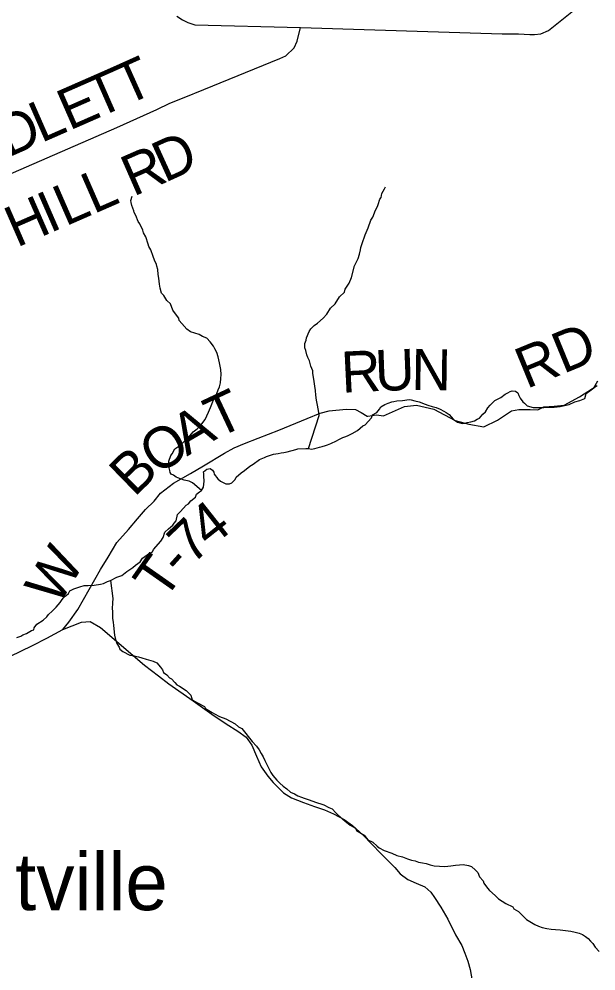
# Model space of a CAD drawing. Extents: x 1310247 to 1664935, y 235267 to 584339.
# Drawn here: x 1471891 to 1476105, y 339195 to 346148 of the extents above; entities that cross this region are included whole.
import ezdxf

# ---------------------------------------------------------------- set-up
doc = ezdxf.new("R2010")
doc.units = 0
for name, color, linetype in [('GM_X_County_Road', 7, 'Continuous'), ('GM_X_Minor_River', 7, 'Continuous'), ('GM_X_Township_Road', 7, 'Continuous'), ('GM_X_Township_Road_Text', 7, 'Continuous'), ('GM_X_Unincorporated_Text', 7, 'Continuous')]:
    doc.layers.add(name, color=color, linetype=linetype)

msp = doc.modelspace()

# ---------------------------------------------------------------- linework, layer by layer
at = {"layer": 'GM_X_County_Road'}
for points in [[(1473043.3, 346168.3), (1473084.6, 346142.9), (1473124.6, 346123), (1473175.2, 346105.6), (1473945.7, 346085.6), (1475419.6, 346041.1), (1475538.9, 346040.1), (1475621.5, 346034.4), (1475655.5, 346035.6), (1475702, 346040.1), (1475757.7, 346063.9), (1475978.4, 346238.9)], [(1471823.6, 341491.5), (1471989.8, 341571.5), (1472093.3, 341625.1), (1472210.2, 341689.5), (1472345.8, 341742.6), (1472409.4, 341748.6), (1472486.7, 341704.7), (1472806.2, 341427.6), (1472909.2, 341350.4), (1472984.9, 341291.3), (1473162.1, 341167.1), (1473298.4, 341070.2), (1473402.9, 340999), (1473489.2, 340947.5), (1473549.7, 340903.6), (1473592.2, 340843.1), (1473625.5, 340764.3), (1473658.8, 340685.5), (1473707.3, 340617.4), (1473746.6, 340570.4), (1473783, 340534.1), (1473821.8, 340495.5), (1473881.6, 340459.9), (1473968, 340424.2), (1474049.6, 340395.4), (1474123.3, 340372.4), (1474187.7, 340342.5), (1474264.8, 340302.2), (1474326.9, 340257.4), (1474401.7, 340189.5), (1474534, 340053.7), (1474636.4, 339951.3), (1474675.5, 339905.3), (1474731.9, 339862.7), (1474791.7, 339836.2), (1474853.9, 339809.8), (1474898.7, 339770.6), (1474926.3, 339731.5), (1474972.4, 339661.4), (1475021.9, 339573.9), (1475079.4, 339457.7), (1475124.2, 339380.6), (1475147.2, 339325.4), (1475170.3, 339265.6), (1475186.4, 339205.8), (1475201.3, 339121.8)]]:
    msp.add_lwpolyline(points, dxfattribs=at)
at = {"layer": 'GM_X_Minor_River'}
for points in [[(1474004.1, 343011.3), (1474082.6, 343251.8), (1474080.9, 343273.9), (1474071.9, 343328.3), (1474062.5, 343364.6), (1474059.1, 343400.8), (1474055.7, 343434.9), (1474052.3, 343467.1), (1474046.9, 343501.3), (1474041.4, 343531.5), (1474035.9, 343559.8), (1474036.2, 343577.8), (1474022.8, 343612.2), (1474013.4, 343652.5), (1473999.8, 343676.8), (1473994.1, 343695), (1473984.7, 343727.2), (1473979, 343745.4), (1473979.5, 343777.5), (1473988.1, 343803.5), (1473990.4, 343819.5), (1474009.3, 343865.3), (1474021.7, 343885.2), (1474046.2, 343908.9), (1474070.7, 343926.5), (1474111.6, 343963.9), (1474138.2, 343991.6), (1474167.1, 344035.2), (1474199.9, 344066.8), (1474230.9, 344118.5), (1474267.8, 344154), (1474274.2, 344175.9), (1474303.1, 344219.6), (1474320, 344261.4), (1474341.6, 344345.4), (1474368.7, 344399.1), (1474377.3, 344431.1), (1474383.9, 344463.1), (1474388.2, 344479), (1474396.8, 344509), (1474418.1, 344572.9), (1474434.8, 344606.7), (1474441.1, 344622.6), (1474460.2, 344678.5), (1474474.7, 344700.3), (1474493.7, 344752.2), (1474508.3, 344780), (1474514.5, 344794), (1474527.3, 344831.9), (1474535.6, 344845.8), (1474542.1, 344873.8), (1474560.8, 344907.6), (1474567.1, 344921.5)], [(1473224.7, 342703.5), (1473157.1, 342759.8), (1473133.2, 342772.2), (1473097.2, 342780.9), (1473071.2, 342789.3), (1473051.2, 342795.7), (1473037.3, 342802), (1473019.5, 342816.3), (1473001.5, 342822.7), (1472993.7, 342836.8), (1472991.9, 342850.9), (1472988.3, 342871.1), (1472984.6, 342887.2), (1472985.1, 342919.3), (1472999.9, 342959.2), (1473010.2, 342973.1), (1473029, 343008.9), (1473065.6, 343032.4), (1473100.4, 343065.9), (1473129, 343091.5), (1473163.9, 343133.1), (1473192.4, 343154.7), (1473225.3, 343192.2), (1473249.9, 343222), (1473275, 343277.7), (1473289.7, 343309.6), (1473298.2, 343335.5), (1473306.6, 343353.5), (1473315, 343373.4), (1473325.4, 343393.3), (1473335.8, 343413.2), (1473346.3, 343439.1), (1473354.7, 343461), (1473363.3, 343491), (1473365.9, 343523.1), (1473368.4, 343551.1), (1473365.1, 343589.4), (1473355.9, 343637.7), (1473344.7, 343680), (1473335.2, 343712.3), (1473321.6, 343738.7), (1473311.9, 343758.9), (1473286.4, 343791.5), (1473262.7, 343818), (1473230.8, 343828.5), (1473206.9, 343843), (1473142.9, 343862.2), (1473117.2, 343882.7), (1473079.8, 343923.5), (1473060.1, 343945.9), (1473058.3, 343962), (1473032.8, 343994.5), (1473015.2, 344020.9), (1472995.9, 344067.4), (1472970.3, 344092), (1472948.8, 344128.5), (1472931.1, 344146.8), (1472921.7, 344183.1), (1472916.1, 344211.3), (1472912.9, 344255.5), (1472907.4, 344281.7), (1472904, 344317.9), (1472896.4, 344342.1), (1472894.7, 344356.2), (1472881.1, 344386.5), (1472869.6, 344412.8), (1472854.4, 344461.3), (1472838.8, 344487.6), (1472835, 344503.7), (1472815.9, 344556.2), (1472800.4, 344586.6), (1472794.7, 344604.8), (1472773.4, 344651.3), (1472759.7, 344669.6), (1472744.4, 344712), (1472732.7, 344734.3), (1472728.9, 344748.4), (1472715.6, 344786.8), (1472709.9, 344809), (1472708.2, 344823), (1472716.8, 344855)], [(1475534.9, 343416.6), (1475542.6, 343398.4), (1475552.3, 343378.1), (1475569.9, 343351.7), (1475583.8, 343343.5), (1475603.6, 343323), (1475645.6, 343310.3), (1475675.7, 343309.7), (1475703.9, 343311.3), (1475724, 343310.9), (1475762.2, 343312.3), (1475800.4, 343313.6), (1475844.7, 343318.9), (1475874.9, 343324.4), (1475909.2, 343331.8), (1475949.8, 343351.2), (1475986.2, 343362.6), (1476024.6, 343376), (1476033.3, 343412), (1476059.8, 343433.6), (1476090.3, 343453.2), (1476119.4, 343504.8)], [(1473112.2, 342597), (1473128.5, 342606.7), (1473144.9, 342628.5), (1473179.6, 342656), (1473186, 342678), (1473208.4, 342693.7), (1473224.7, 342703.5), (1473239.2, 342729.3), (1473242, 342773.4), (1473240.7, 342809.6), (1473241, 342825.6), (1473237.2, 342839.8), (1473261.7, 342859.4), (1473285.9, 342865), (1473303.8, 342852.7), (1473313.5, 342838.5), (1473317.3, 342824.3), (1473342.8, 342789.8), (1473362.6, 342773.4), (1473402.4, 342752.6), (1473428.6, 342752.1), (1473444.8, 342759.9), (1473469.4, 342785.6), (1473477.7, 342801.5), (1473512.4, 342833), (1473536.9, 342850.7), (1473577.6, 342882.1), (1473602, 342895.7), (1473646.9, 342931.1), (1473683.3, 342944.5), (1473699.5, 342952.3), (1473750.1, 342969.5), (1473784.3, 342974.9), (1473806.5, 342980.6), (1473824.7, 342982.3), (1473848.9, 342987.9), (1473911.5, 343002.8), (1473927.6, 343008.6), (1473986, 343011.6), (1474004.1, 343011.3), (1474026.1, 343006.9), (1474050.3, 343010.5), (1474086.7, 343021.9), (1474104.8, 343025.6), (1474129.1, 343033.2), (1474143.3, 343039), (1474167.5, 343046.6), (1474210.1, 343068), (1474226.4, 343077.7), (1474256.8, 343091.3), (1474270.9, 343097), (1474291.2, 343104.7), (1474323.6, 343120.2), (1474362.2, 343141.6), (1474403, 343177.1), (1474419.2, 343184.8), (1474464.4, 343234.2), (1474472.8, 343256.2), (1474503.3, 343273.7), (1474523.8, 343297.5), (1474534.2, 343315.4), (1474562.6, 343332.9), (1474586.9, 343342.6), (1474613.2, 343352.1), (1474629.3, 343353.9), (1474651.5, 343359.5), (1474691.8, 343362.8), (1474740.1, 343368), (1474756.2, 343365.8), (1474782.2, 343359.3), (1474814.2, 343352.7), (1474858.1, 343333.9), (1474876.1, 343327.5), (1474908, 343317), (1474938.1, 343310.4), (1474968, 343297.8), (1474993.9, 343283.3), (1475011.8, 343273), (1475031.6, 343260.6), (1475063.2, 343225.9), (1475092.9, 343203.3), (1475110.9, 343199), (1475130.9, 343194.7), (1475147, 343196.4), (1475165.2, 343200.1), (1475191.4, 343205.7), (1475217.7, 343213.2), (1475238, 343224.9), (1475254.2, 343232.7), (1475278.9, 343262.4), (1475297.3, 343278.1), (1475315.9, 343307.9), (1475332.3, 343327.7), (1475367.1, 343361.2), (1475409.7, 343382.6), (1475442.3, 343408.1), (1475460.6, 343417.8), (1475478.8, 343427.6), (1475493, 343431.3), (1475517.1, 343428.9), (1475534.9, 343416.6)], [(1471874.7, 341630.2), (1471903, 341639.8), (1471917.2, 341649.5), (1471945.5, 341659.1), (1471982.1, 341680.6), (1471998.3, 341686.3), (1472000.5, 341700.3), (1472021.1, 341728.1), (1472065.9, 341757.5), (1472092.5, 341781.1), (1472106.9, 341798.9), (1472133.4, 341822.6), (1472162.1, 341852.2), (1472190.8, 341885.8), (1472201.2, 341901.7), (1472219.7, 341927.5), (1472234, 341937.3), (1472252.4, 341953.1), (1472262.7, 341971), (1472291.1, 341986.5), (1472335.6, 342001.8), (1472365.9, 342009.4), (1472396.1, 342010.8), (1472438.4, 342014.1), (1472484.7, 342021.4), (1472506.9, 342025), (1472537.3, 342038.5), (1472559.5, 342046.2), (1472604.2, 342071.5), (1472640.6, 342083), (1472679.3, 342112.4), (1472722.1, 342141.8), (1472740.5, 342159.6), (1472775.1, 342183.1), (1472791.6, 342208.9), (1472842.5, 342246.2), (1472864.8, 342255.8), (1472873.2, 342273.8), (1472926.6, 342335.1), (1472943.1, 342360.9), (1472955.9, 342400.8), (1472982.4, 342424.5), (1473013.1, 342452.1), (1473023.4, 342466), (1473037.8, 342481.8), (1473048.7, 342529.8), (1473071.2, 342551.5), (1473112.2, 342597)], [(1472559.5, 342046.2), (1472575, 341914.3), (1472574.4, 341884.2), (1472571.6, 341840.1), (1472573.3, 341822), (1472574.4, 341769.7), (1472577.9, 341741.6), (1472579.5, 341719.4), (1472588.2, 341647), (1472595.7, 341616.7), (1472605.2, 341586.4), (1472622.8, 341560), (1472626.6, 341545.9), (1472648.4, 341529.5), (1472700.2, 341502.5), (1472732.2, 341495.9), (1472748.2, 341491.6), (1472762.3, 341489.3), (1472788.3, 341482.9), (1472820.2, 341472.3), (1472870.2, 341457.4), (1472896.1, 341444.9), (1472923.7, 341414.3), (1472939.4, 341393.9), (1472945.1, 341375.7), (1472970.9, 341357.2), (1472988.6, 341334.8), (1473004.6, 341328.5), (1473028.2, 341302), (1473044, 341285.6), (1473063.9, 341275.3), (1473111.5, 341242.3), (1473145.1, 341209.6), (1473154.5, 341175.3), (1473194.3, 341152.5), (1473246.1, 341127.5), (1473253.9, 341111.3), (1473301.6, 341082.4), (1473319.5, 341072), (1473355.3, 341053.3), (1473401.2, 341036.5), (1473468.9, 340999.2), (1473492.7, 340978.7), (1473518.6, 340966.2), (1473548, 340929.5), (1473563.7, 340907.1), (1473593.2, 340870.5), (1473624.8, 340837.8), (1473644.3, 340809.3), (1473659.9, 340782.9), (1473673.6, 340758.6), (1473687.2, 340732.3), (1473700.7, 340703.9), (1473716.3, 340673.5), (1473729.8, 340645.1), (1473745.5, 340622.8), (1473759.3, 340606.5), (1473775, 340588.1), (1473794.7, 340565.7), (1473820.5, 340545.2), (1473846.2, 340524.6), (1473873.9, 340502), (1473901.8, 340487.5), (1473927.7, 340473), (1473953.7, 340464.5), (1473973.6, 340456.1), (1474001.6, 340447.6), (1474063.5, 340424.5), (1474103.5, 340413.7), (1474117.4, 340407.5), (1474153.3, 340388.8), (1474177.2, 340378.3), (1474204.8, 340349.7), (1474220.6, 340335.4), (1474254.3, 340306.7), (1474272, 340288.3), (1474309.7, 340259.5), (1474349.5, 340236.7), (1474355.2, 340220.6), (1474410.9, 340187.5), (1474438.4, 340152.8), (1474474.3, 340136.1), (1474507.9, 340105.4), (1474521.8, 340095.1), (1474557.6, 340074.4), (1474613.5, 340055.4), (1474651.4, 340038.7), (1474691.4, 340028), (1474727.3, 340013.3), (1474757.3, 340004.7), (1474785.4, 339998.2), (1474809.3, 339989.8), (1474837.4, 339985.3), (1474865.4, 339978.8), (1474893.4, 339970.2), (1474923.4, 339963.7), (1474961.6, 339961), (1475001.7, 339958.3), (1475044, 339961.6), (1475080.2, 339967), (1475108.4, 339970.5)], [(1475108.4, 339970.5), (1475134.6, 339972.1), (1475174.7, 339965.4), (1475196.7, 339959), (1475226.3, 339930.3), (1475242.1, 339914), (1475255.6, 339881.6), (1475281.2, 339853.1), (1475284.9, 339836.9), (1475312.4, 339800.3), (1475328.1, 339781.9), (1475367.7, 339745.1), (1475393.4, 339722.5), (1475447, 339687.5), (1475496.8, 339662.5), (1475504.6, 339648.3), (1475538.4, 339629.6), (1475572, 339596.9), (1475597.7, 339570.4), (1475633.5, 339549.6), (1475659.3, 339535.1), (1475685.2, 339522.6), (1475713.2, 339512.1), (1475745.2, 339505.5), (1475777.3, 339501), (1475809.4, 339498.4), (1475843.5, 339495.8), (1475883.6, 339491.1), (1475921.7, 339486.4), (1475953.7, 339477.8), (1475981.8, 339471.3), (1476007.7, 339460.8), (1476029.5, 339446.4), (1476047.4, 339432), (1476065.1, 339411.6), (1476082.9, 339395.2), (1476100.5, 339368.8), (1476128.1, 339336.2)]]:
    msp.add_lwpolyline(points, dxfattribs=at)
at = {"layer": 'GM_X_Township_Road'}
for points in [[(1470923.8, 344624.6), (1472606, 345354.7), (1472897.9, 345487.2), (1472991.3, 345534.8), (1473096.5, 345576.1), (1473240.3, 345634.4), (1473797, 345860.1), (1473839.5, 345879), (1473900.4, 345939), (1473921.7, 345987), (1473945.7, 346085.6)], [(1474438, 343248.3), (1474502.6, 343256), (1474554, 343250.6), (1474706.4, 343318.3), (1474793.3, 343327.9), (1474921, 343298.3), (1475076.1, 343216.5), (1475175.6, 343189.9), (1475285, 343169.4), (1475385.9, 343217.9), (1475487, 343285.3), (1475542.7, 343297), (1475624.7, 343297), (1475679.4, 343292.5), (1475723.7, 343316.3), (1475798.7, 343321.4), (1475873.2, 343327.5), (1475985.7, 343388.3), (1476114.1, 343471.1)], [(1472210.2, 341689.5), (1472255.1, 341743.5), (1472319.6, 341836.1), (1472485.7, 342126.3), (1472542.2, 342217), (1472605.2, 342323.6), (1472690.8, 342419.5), (1472757.1, 342496.6), (1472814, 342565.7), (1472877.6, 342626.6), (1472923.3, 342684), (1473018.4, 342757.9), (1473144.3, 342829.6), (1473237.6, 342883.8), (1473392, 342977.9), (1473462.3, 343017.1), (1473536.8, 343047.5), (1473637, 343086), (1473789.2, 343145.7), (1473995.7, 343229.6), (1474090.4, 343268.9), (1474156.1, 343287.1), (1474279.3, 343298.7), (1474348.3, 343295.3), (1474390.3, 343275), (1474434.3, 343247.9), (1474438, 343248.3)]]:
    msp.add_lwpolyline(points, dxfattribs=at)

# ---------------------------------------------------------------- texts
at = {"layer": 'GM_X_Township_Road_Text'}
for s, rotation, p in [('T', 24.1471, (1472671.2, 345512.6)), ('T', 23.71051, (1472463.5, 345421.4)), ('E', 23.69752, (1472257.9, 345331.2)), ('L', 23.69661, (1472052.4, 345241)), ('D', 23.69821, (1471810.7, 345134.9)), ('D', 24.49461, (1472954.5, 344949.8)), ('R', 23.68781, (1472724.8, 344848.9)), ('L', 23.62569, (1472434.2, 344721.8)), ('I', 23.62446, (1472115.7, 344582.5)), ('L', 23.63106, (1472228.6, 344631.8)), ('H', 23.62479, (1471873.9, 344476.7)), ('RD', 22.3529, (1475597.3, 343444.3)), ('R', 2.81329, (1474250.4, 343417.9)), ('U', 2.12602, (1474495.6, 343429.9)), ('N', 359.23316, (1474755.4, 343439.7)), ('T', 25.21754, (1473338.3, 343081.4)), ('A', 30.20845, (1473116.3, 342951.8)), ('O', 32.25676, (1472895.5, 342812.4)), ('B', 44.20651, (1472731.8, 342650.8)), ('4', 38.29693, (1473282.3, 342277.6)), ('7', 43.66042, (1473154.2, 342154.9)), ('W', 58.53613, (1472175.5, 341852.4)), ('T', 54.97971, (1472953.2, 341891.4)), ('-', 48.02613, (1473076, 342067.7))]:
    msp.add_text(s, height=300, rotation=rotation, dxfattribs=at).set_placement(p)
at = {"layer": 'GM_X_Unincorporated_Text'}
msp.add_text('Clermontville', height=417, rotation=0.00001, dxfattribs=at).set_placement((1469755, 339638.9))

doc.saveas('drawing.dxf')
